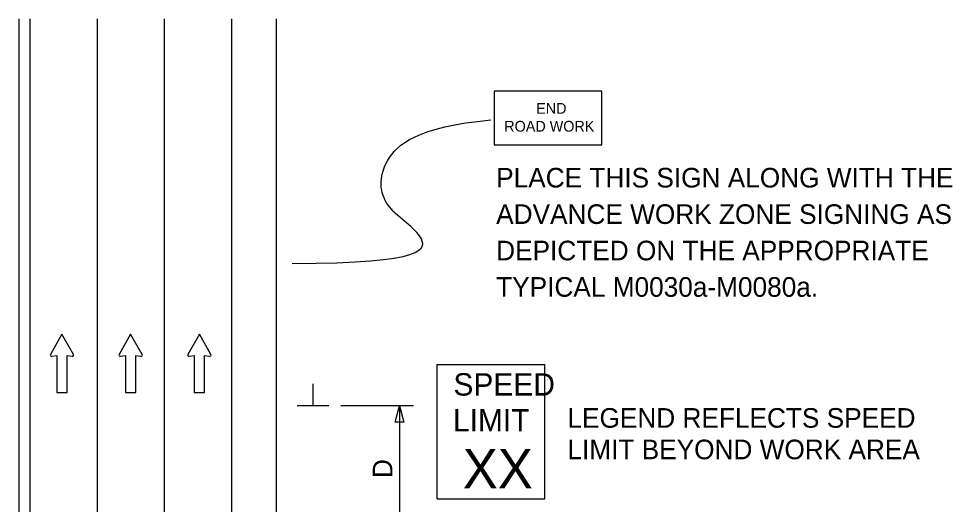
# Model space of a CAD drawing. Extents: x 16751 to 18475, y 5726 to 6923.
# Drawn here: x 17076.1 to 17409.5, y 6738.4 to 6911.7 of the extents above; entities that cross this region are included whole.
import ezdxf

# ---------------------------------------------------------------- set-up
doc = ezdxf.new("R2010")
doc.units = 0
for name, color, linetype in [('ALI_LEGAL_EX', 7, 'Continuous'), ('MT_SCRATCH_LEVEL_E', 7, 'Continuous'), ('PAVT_EDGE_EX', 7, 'Continuous'), ('TRAFFIC_SIGNS_PR', 7, 'Continuous'), ('TYPICAL_TEXT_DIMEN_PR', 7, 'Continuous')]:
    doc.layers.add(name, color=color, linetype=linetype)

msp = doc.modelspace()

# ---------------------------------------------------------------- linework, layer by layer
at = {"layer": 'ALI_LEGAL_EX'}
for p, q in [((17104.08, 6911.72), (17104.08, 6082.53)), ((17128.08, 6911.72), (17128.08, 6082.53)), ((17128.08, 6911.72), (17128.08, 6082.53))]:
    msp.add_line(p, q, dxfattribs=at)
for points in [[(17104.08, 6911.72), (17104.08, 6886.72)], [(17128.08, 6911.72), (17128.08, 6886.72)], [(17104.08, 6811.72), (17104.08, 6786.72)], [(17128.08, 6811.72), (17128.08, 6786.72)]]:
    msp.add_lwpolyline(points, dxfattribs=at)
at = {"layer": 'MT_SCRATCH_LEVEL_E'}
for p, q in [((17091.51, 6799.13), (17087.4, 6791.89)), ((17091.51, 6799.13), (17087.4, 6791.89)), ((17095.66, 6791.89), (17091.51, 6799.13)), ((17095.66, 6791.89), (17091.51, 6799.13)), ((17116.04, 6799.13), (17111.93, 6791.89)), ((17116.04, 6799.13), (17111.93, 6791.89)), ((17120.19, 6791.89), (17116.04, 6799.13)), ((17120.19, 6791.89), (17116.04, 6799.13)), ((17140.6, 6799.13), (17136.49, 6791.89)), ((17140.6, 6799.13), (17136.49, 6791.89)), ((17144.75, 6791.89), (17140.6, 6799.13)), ((17144.75, 6791.89), (17140.6, 6799.13)), ((17087.89, 6791.21), (17089.66, 6791.52)), ((17087.89, 6791.21), (17089.66, 6791.52)), ((17089.66, 6791.52), (17089.66, 6778.26)), ((17089.66, 6791.52), (17089.66, 6778.26)), ((17093.4, 6778.26), (17093.4, 6791.52)), ((17093.4, 6791.52), (17095.18, 6791.21)), ((17093.4, 6778.26), (17093.4, 6791.52)), ((17093.4, 6791.52), (17095.18, 6791.21)), ((17112.41, 6791.21), (17114.19, 6791.52)), ((17112.41, 6791.21), (17114.19, 6791.52)), ((17114.19, 6791.52), (17114.19, 6778.26)), ((17114.19, 6791.52), (17114.19, 6778.26)), ((17117.93, 6778.26), (17117.93, 6791.52)), ((17117.93, 6791.52), (17119.71, 6791.21)), ((17117.93, 6778.26), (17117.93, 6791.52)), ((17117.93, 6791.52), (17119.71, 6791.21)), ((17136.97, 6791.21), (17138.75, 6791.52)), ((17136.97, 6791.21), (17138.75, 6791.52)), ((17138.75, 6791.52), (17138.75, 6778.26)), ((17138.75, 6791.52), (17138.75, 6778.26)), ((17142.49, 6778.26), (17142.49, 6791.52)), ((17142.49, 6791.52), (17144.27, 6791.21)), ((17142.49, 6778.26), (17142.49, 6791.52)), ((17142.49, 6791.52), (17144.27, 6791.21)), ((17089.66, 6778.26), (17093.4, 6778.26)), ((17089.66, 6778.26), (17093.4, 6778.26)), ((17114.19, 6778.26), (17117.93, 6778.26)), ((17114.19, 6778.26), (17117.93, 6778.26)), ((17138.75, 6778.26), (17142.49, 6778.26)), ((17138.75, 6778.26), (17142.49, 6778.26))]:
    msp.add_line(p, q, dxfattribs=at)
for centre, start, end in [((17087.81, 6791.66), 150.4248, 279.9638), ((17087.81, 6791.66), 150.4248, 279.9638), ((17095.25, 6791.67), 260.0362, 29.7731), ((17095.25, 6791.67), 260.0362, 29.7731), ((17112.34, 6791.66), 150.4248, 279.9638), ((17112.34, 6791.66), 150.4248, 279.9638), ((17119.78, 6791.67), 260.0362, 29.7731), ((17119.78, 6791.67), 260.0362, 29.7731), ((17136.9, 6791.66), 150.4248, 279.9638), ((17136.9, 6791.66), 150.4248, 279.9638), ((17144.34, 6791.67), 260.0362, 29.7731), ((17144.34, 6791.67), 260.0362, 29.7731)]:
    msp.add_arc(centre, 0.463, start, end, dxfattribs=at)
at = {"layer": 'PAVT_EDGE_EX'}
for p, q in [((17076.08, 6911.72), (17076.08, 6082.53)), ((17080.08, 6911.72), (17080.08, 6082.53)), ((17152.08, 6911.72), (17152.08, 6082.53)), ((17168.08, 6911.72), (17168.08, 6082.53))]:
    msp.add_line(p, q, dxfattribs=at)
at = {"layer": 'TRAFFIC_SIGNS_PR'}
for p, q in [((17225.56, 6788.31), (17263.96, 6788.31)), ((17225.56, 6740.31), (17225.56, 6788.31)), ((17263.96, 6740.31), (17263.96, 6788.31)), ((17225.56, 6740.31), (17263.96, 6740.31))]:
    msp.add_line(p, q, dxfattribs=at)
msp.add_lwpolyline([(17245.89, 6866.65), (17284.29, 6866.65), (17284.29, 6885.85), (17245.89, 6885.85)], close=True, dxfattribs=at)
at = {"layer": 'TYPICAL_TEXT_DIMEN_PR'}
for p, q in [((17181.2, 6773.53), (17181.2, 6781.32)), ((17186.83, 6773.53), (17175.58, 6773.53)), ((17217.08, 6773.53), (17191.08, 6773.53)), ((17210.51, 6767.67), (17212.08, 6773.53)), ((17212.08, 6773.53), (17212.08, 6723.53)), ((17212.08, 6773.53), (17213.65, 6767.67)), ((17212.08, 6767.67), (17210.51, 6767.67)), ((17213.65, 6767.67), (17212.08, 6767.67))]:
    msp.add_line(p, q, dxfattribs=at)
msp.add_open_spline([(17173.74, 6824.35), (17222.2, 6824.35), (17222.2, 6835.11), (17205.42, 6843.87), (17203.99, 6860.68), (17218.35, 6873.16), (17244.68, 6875.56)], degree=3, dxfattribs=at)

# ---------------------------------------------------------------- texts
at = {"layer": 'TRAFFIC_SIGNS_PR'}
for s, height, p in [('END', 3.831, (17260.89, 6877.78)), ('ROAD WORK', 3.831, (17249.5, 6871.4)), ('PLACE THIS SIGN ALONG WITH THE', 7, (17246.6, 6851.46)), ('ADVANCE WORK ZONE SIGNING AS', 7, (17246.6, 6838.46)), ('DEPICTED ON THE APPROPRIATE', 7, (17246.6, 6825.46)), ('TYPICAL M0030a-M0080a.', 7, (17246.6, 6812.46)), ('SPEED', 8, (17231.33, 6777.18)), ('LIMIT', 8, (17231.17, 6764.38)), ('XX', 14.031, (17234.68, 6744.07))]:
    msp.add_text(s, height=height, dxfattribs=at).set_placement(p)
at = {"layer": 'TYPICAL_TEXT_DIMEN_PR'}
for s, p in [('LEGEND REFLECTS SPEED', (17272.05, 6765.71)), ('LIMIT BEYOND WORK AREA', (17272.05, 6754.46))]:
    msp.add_text(s, height=7, dxfattribs=at).set_placement(p)
msp.add_text('D', height=7, rotation=90, dxfattribs=at).set_placement((17209.52, 6747.75))

doc.saveas('drawing.dxf')
